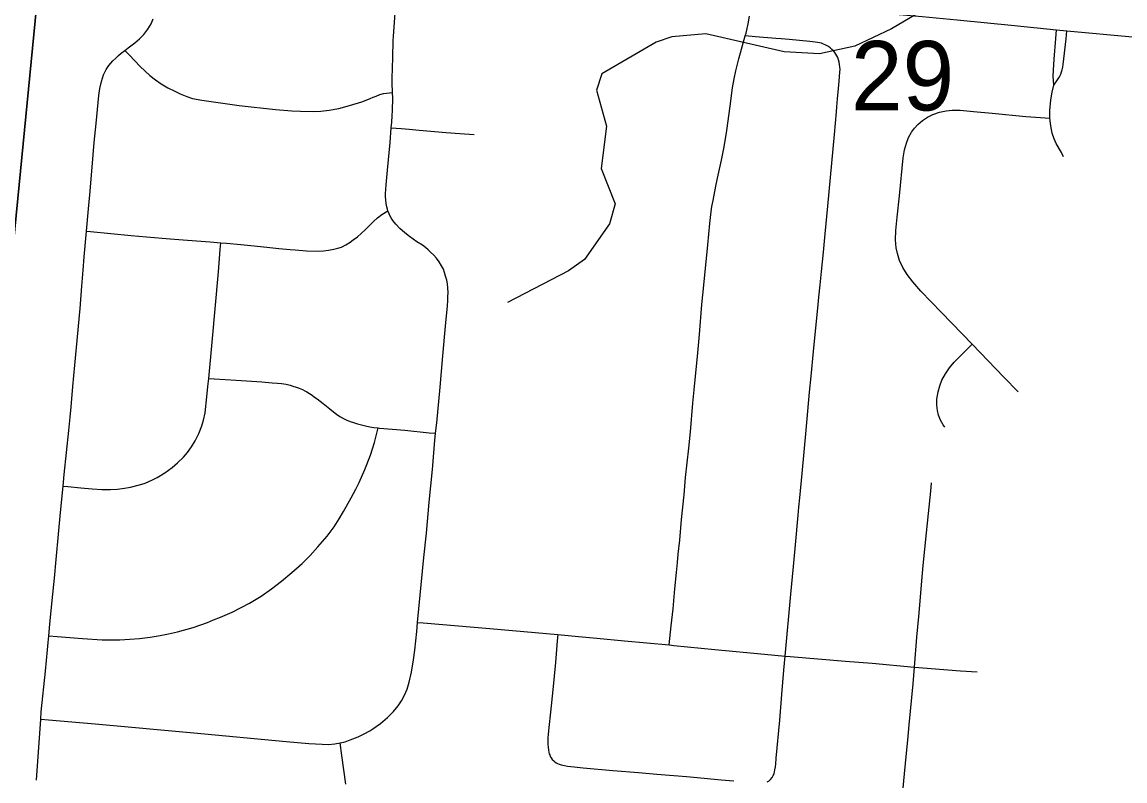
# Model space of a CAD drawing. Extents: x 0 to 34, y 0 to 22.
# Drawn here: x 7.009 to 7.674, y 20.166 to 20.623 of the extents above; entities that cross this region are included whole.
import ezdxf

# ---------------------------------------------------------------- set-up
doc = ezdxf.new("R2010")
doc.units = 0
for name, color, linetype in [('GM_X_City_Street', 7, 'Continuous'), ('GM_X_Corporation', 7, 'Continuous'), ('GM_X_County_Road', 7, 'Continuous'), ('GM_X_Minor_River', 7, 'Continuous'), ('GM_X_Section_Text', 7, 'Continuous')]:
    doc.layers.add(name, color=color, linetype=linetype)

msp = doc.modelspace()

# ---------------------------------------------------------------- linework, layer by layer
at = {"layer": 'GM_X_City_Street'}
for points in [[(7.01765, 20.16616), (7.02028, 20.20299), (7.02059, 20.20733), (7.02311, 20.23181), (7.02439, 20.24474), (7.0248, 20.24906), (7.02517, 20.25317), (7.02578, 20.2602), (7.02715, 20.27441), (7.02852, 20.28798), (7.02955, 20.29912), (7.03104, 20.31451), (7.03224, 20.32749), (7.03378, 20.3434), (7.03445, 20.35036), (7.03714, 20.37693), (7.03794, 20.38497), (7.03856, 20.39114), (7.03966, 20.40351), (7.04072, 20.41641), (7.0418, 20.4269), (7.04391, 20.45041), (7.04501, 20.464), (7.04573, 20.47368), (7.0465, 20.48157), (7.04748, 20.49268), (7.04788, 20.49705), (7.04911, 20.51056), (7.04944, 20.51478), (7.0498, 20.51903), (7.05118, 20.53564), (7.05249, 20.55049), (7.05357, 20.56203), (7.05525, 20.57887), (7.05587, 20.58308), (7.05688, 20.58721), (7.05814, 20.59136), (7.05967, 20.59452), (7.06135, 20.597), (7.06367, 20.59978), (7.06558, 20.60145), (7.06717, 20.60294), (7.06877, 20.60435), (7.07098, 20.60608), (7.07301, 20.60762), (7.07687, 20.61057), (7.07981, 20.61297), (7.08247, 20.61573), (7.08479, 20.61879), (7.08671, 20.62213), (7.08798, 20.62506)], [(7.02028, 20.20299), (7.02498, 20.20258), (7.05303, 20.20009), (7.11249, 20.19461), (7.16815, 20.18948), (7.18179, 20.18821), (7.18987, 20.18778), (7.19371, 20.18768), (7.19751, 20.18804), (7.20083, 20.18865), (7.20367, 20.18938), (7.20682, 20.19045), (7.21162, 20.19236), (7.21606, 20.19457), (7.21788, 20.19558), (7.21853, 20.19588), (7.22038, 20.19703), (7.22496, 20.20024), (7.22927, 20.20392), (7.23283, 20.20751), (7.23565, 20.21093), (7.23779, 20.21409), (7.2396, 20.21745), (7.24105, 20.22096), (7.24234, 20.22519), (7.24373, 20.23132), (7.24494, 20.2387), (7.24568, 20.2446), (7.24693, 20.2557), (7.24745, 20.26125), (7.25116, 20.30033), (7.2528, 20.31513), (7.25448, 20.33368), (7.25634, 20.35336), (7.25652, 20.35582), (7.25759, 20.36865), (7.25828, 20.37526), (7.25892, 20.38148), (7.26093, 20.40296), (7.26261, 20.42201), (7.26432, 20.43983), (7.26536, 20.45208), (7.26559, 20.45529), (7.2657, 20.45766), (7.26585, 20.45985), (7.2657, 20.46285), (7.26541, 20.46533), (7.26496, 20.4676), (7.26431, 20.47001), (7.26365, 20.47227), (7.26299, 20.4741), (7.2619, 20.47622), (7.26051, 20.47863), (7.25891, 20.48075), (7.25715, 20.48264), (7.25525, 20.48447), (7.25379, 20.48586), (7.25226, 20.48724), (7.25029, 20.48863), (7.24699, 20.49059), (7.2425, 20.49383), (7.23964, 20.49616), (7.2367, 20.49872), (7.23436, 20.50127), (7.23256, 20.50354), (7.23152, 20.50514), (7.23071, 20.5066), (7.22983, 20.5085), (7.22957, 20.50935), (7.22925, 20.51035), (7.22888, 20.51171), (7.22845, 20.51376), (7.22823, 20.5158), (7.22808, 20.51792), (7.22815, 20.51982), (7.22823, 20.5223), (7.22837, 20.52494), (7.22919, 20.53381), (7.23084, 20.55047), (7.23158, 20.55941), (7.23186, 20.56288), (7.23218, 20.56661), (7.23231, 20.56973), (7.23239, 20.57723), (7.2323, 20.58074), (7.23217, 20.58652), (7.23237, 20.59824), (7.23241, 20.59887), (7.23247, 20.60197), (7.23272, 20.61188), (7.23288, 20.61466), (7.23386, 20.62847)], [(7.3991, 20.24769), (7.39953, 20.2516), (7.40037, 20.25924), (7.40152, 20.26941), (7.40254, 20.2815), (7.40349, 20.29134), (7.40406, 20.29745), (7.40454, 20.30232), (7.40542, 20.31091), (7.40646, 20.32328), (7.40805, 20.3381), (7.40895, 20.34862), (7.41083, 20.36639), (7.41189, 20.37615), (7.4134, 20.39346), (7.41416, 20.4015), (7.41631, 20.42375), (7.41738, 20.43488), (7.41885, 20.45281), (7.41995, 20.46447), (7.42236, 20.48889), (7.42359, 20.50167), (7.42392, 20.50535), (7.42415, 20.50718), (7.42436, 20.50902), (7.42486, 20.51205), (7.42558, 20.51566), (7.4272, 20.52417), (7.42814, 20.52903), (7.43061, 20.53994), (7.43226, 20.54787), (7.4339, 20.5577), (7.43586, 20.57248), (7.43729, 20.5834), (7.43824, 20.589), (7.43923, 20.59382), (7.44102, 20.60101), (7.44495, 20.61482), (7.44543, 20.61653), (7.44667, 20.62202), (7.44752, 20.6267)], [(7.63088, 20.58506), (7.6307, 20.58817), (7.63061, 20.59039), (7.63079, 20.59404), (7.63122, 20.60069), (7.63212, 20.61315), (7.63251, 20.61852)], [(7.63088, 20.58506), (7.63309, 20.58826), (7.6339, 20.58944), (7.63472, 20.59086), (7.63513, 20.59176), (7.63564, 20.59319), (7.636, 20.59438), (7.63635, 20.59592), (7.63667, 20.59754), (7.63835, 20.61297), (7.63888, 20.61792)], [(7.45927, 20.16574), (7.46021, 20.16657), (7.46114, 20.16774), (7.46183, 20.16896), (7.46229, 20.16997), (7.4626, 20.17115), (7.46285, 20.17243), (7.46309, 20.1742), (7.4633, 20.17585), (7.46358, 20.17951), (7.46585, 20.20233), (7.467, 20.21774), (7.46822, 20.2324), (7.4689, 20.24094), (7.4725, 20.27827), (7.474, 20.29496), (7.4752, 20.30794), (7.47688, 20.32583), (7.47731, 20.33077), (7.47785, 20.3363), (7.47931, 20.35111), (7.48175, 20.37709), (7.4837, 20.39999), (7.48464, 20.40976), (7.48614, 20.42455), (7.48888, 20.45296), (7.48925, 20.45729), (7.49006, 20.4647), (7.49085, 20.47272), (7.49209, 20.48442), (7.49313, 20.49544), (7.49463, 20.5121), (7.49867, 20.55534), (7.49989, 20.56892), (7.50017, 20.57201), (7.50061, 20.57694), (7.50122, 20.58312), (7.50164, 20.58742), (7.50203, 20.59294), (7.50206, 20.59464), (7.50197, 20.59595), (7.50182, 20.59748), (7.50155, 20.59889), (7.50113, 20.60045), (7.50067, 20.6017), (7.50011, 20.60284), (7.49961, 20.60375), (7.49889, 20.6048), (7.49825, 20.60565), (7.49723, 20.60665), (7.4961, 20.60762), (7.49503, 20.60836), (7.49396, 20.609), (7.49313, 20.60944), (7.49207, 20.60987), (7.49083, 20.61032), (7.48966, 20.61062), (7.48844, 20.61085), (7.48718, 20.61106), (7.48382, 20.61151), (7.47146, 20.61266), (7.46653, 20.61308), (7.46344, 20.61331), (7.45107, 20.61432), (7.44495, 20.61482)], [(7.07098, 20.60608), (7.07382, 20.60308), (7.08024, 20.59628), (7.08594, 20.59095), (7.08938, 20.58825), (7.09288, 20.58584), (7.0969, 20.58343), (7.10106, 20.58138), (7.10435, 20.57992), (7.10837, 20.57824), (7.1118, 20.57714), (7.11728, 20.57598), (7.13978, 20.57276), (7.16184, 20.5705), (7.17162, 20.56969), (7.17688, 20.5694), (7.1844, 20.56926), (7.18915, 20.56948), (7.19419, 20.56999), (7.19989, 20.57094), (7.20646, 20.57276), (7.2137, 20.57507), (7.21545, 20.57574), (7.21891, 20.57713), (7.22065, 20.5778), (7.22238, 20.57849), (7.22472, 20.57941), (7.22691, 20.58007), (7.22866, 20.58029), (7.2323, 20.58074)], [(7.63683, 20.54194), (7.63551, 20.54453), (7.63239, 20.54989), (7.63108, 20.5527), (7.62993, 20.55623), (7.62906, 20.56049), (7.62863, 20.5652), (7.62864, 20.56976), (7.6291, 20.57626), (7.62999, 20.58097), (7.63088, 20.58506)], [(7.60944, 20.4002), (7.60074, 20.40906), (7.58178, 20.42896), (7.56327, 20.44803), (7.55079, 20.461), (7.5459, 20.46656), (7.54258, 20.47096), (7.54003, 20.47512), (7.53799, 20.4795), (7.53669, 20.48355), (7.536, 20.48711), (7.53554, 20.49195), (7.53566, 20.49745), (7.53655, 20.50545), (7.53787, 20.51845), (7.54009, 20.54132), (7.54091, 20.54613), (7.54206, 20.55021), (7.54344, 20.55358), (7.54521, 20.55671), (7.54699, 20.55914), (7.549, 20.56136), (7.55173, 20.56373), (7.55475, 20.56572), (7.55798, 20.56736), (7.56194, 20.56882), (7.56607, 20.56971), (7.56968, 20.57004), (7.57457, 20.56999), (7.58257, 20.5692), (7.59372, 20.56818), (7.61415, 20.5662), (7.62287, 20.56559), (7.62863, 20.5652)], [(7.23158, 20.55941), (7.23744, 20.55891), (7.2423, 20.55849), (7.2484, 20.55801), (7.26455, 20.55664), (7.27297, 20.55592), (7.28146, 20.55532)], [(7.04788, 20.49705), (7.05026, 20.49683), (7.07474, 20.49454), (7.08401, 20.49371), (7.09824, 20.4925), (7.10878, 20.49167), (7.12239, 20.49061), (7.12885, 20.49007), (7.13229, 20.48977), (7.14095, 20.48897), (7.14899, 20.48817), (7.15825, 20.48717), (7.16381, 20.48665), (7.1706, 20.48608), (7.17366, 20.4858), (7.18045, 20.48529), (7.18744, 20.48506), (7.19072, 20.48521), (7.19379, 20.48557), (7.19686, 20.48616), (7.19927, 20.48685), (7.20155, 20.48754), (7.20419, 20.48884), (7.20673, 20.49036), (7.20867, 20.49179), (7.2111, 20.49365), (7.21344, 20.49561), (7.2161, 20.49808), (7.21829, 20.50021), (7.22093, 20.50283), (7.22315, 20.50515), (7.22578, 20.50712), (7.22957, 20.50935)], [(7.03378, 20.3434), (7.0366, 20.34313), (7.0444, 20.34239), (7.05121, 20.34174), (7.05699, 20.34138), (7.06224, 20.34135), (7.06651, 20.34162), (7.07076, 20.34218), (7.07438, 20.34283), (7.07975, 20.3441), (7.08321, 20.34524), (7.08767, 20.34722), (7.09036, 20.34863), (7.09506, 20.35151), (7.09952, 20.35473), (7.10276, 20.35752), (7.10624, 20.36095), (7.10862, 20.36373), (7.11119, 20.36714), (7.11342, 20.37077), (7.11557, 20.37515), (7.11738, 20.37969), (7.1184, 20.38319), (7.11929, 20.38761), (7.1204, 20.39721), (7.12106, 20.40342), (7.12153, 20.40829), (7.12367, 20.4302), (7.12732, 20.47256), (7.12849, 20.486), (7.12885, 20.49007)], [(7.56533, 20.37892), (7.56427, 20.38045), (7.56271, 20.38316), (7.56145, 20.38611), (7.56076, 20.38904), (7.56042, 20.39213), (7.5605, 20.39587), (7.56116, 20.40019), (7.56215, 20.40379), (7.56352, 20.40727), (7.56558, 20.41112), (7.56806, 20.41472), (7.57087, 20.41806), (7.57838, 20.42556), (7.58178, 20.42896)], [(7.12153, 20.40829), (7.12485, 20.40808), (7.13814, 20.40723), (7.15359, 20.40622), (7.15974, 20.40566), (7.16292, 20.40542), (7.16528, 20.40517), (7.16809, 20.40477), (7.17063, 20.40417), (7.1723, 20.40371), (7.17412, 20.40314), (7.17602, 20.40247), (7.17805, 20.40158), (7.17936, 20.40089), (7.18073, 20.40017), (7.18222, 20.39923), (7.18382, 20.39821), (7.18535, 20.39713), (7.18682, 20.39608), (7.19051, 20.39317), (7.19458, 20.38994), (7.19869, 20.38666), (7.20089, 20.38521), (7.20265, 20.3842), (7.20441, 20.38335), (7.20671, 20.38245), (7.20877, 20.3818), (7.21116, 20.38104), (7.21359, 20.38034), (7.21609, 20.37969), (7.21865, 20.37924), (7.22106, 20.37883), (7.22372, 20.37851), (7.22446, 20.37841), (7.23966, 20.37706), (7.25446, 20.37563), (7.25828, 20.37526)], [(7.02517, 20.25317), (7.03019, 20.2527), (7.04549, 20.2515), (7.05735, 20.25081), (7.06289, 20.25083), (7.06785, 20.2508), (7.07391, 20.25109), (7.07975, 20.25157), (7.08613, 20.25244), (7.09231, 20.25338), (7.0972, 20.25436), (7.10259, 20.25559), (7.11213, 20.25828), (7.12082, 20.26131), (7.12447, 20.26273), (7.12852, 20.26433), (7.13281, 20.26624), (7.13561, 20.26751), (7.14606, 20.27286), (7.15318, 20.27709), (7.15936, 20.28146), (7.16534, 20.28603), (7.17158, 20.29133), (7.17777, 20.29684), (7.18275, 20.30159), (7.18731, 20.30679), (7.19289, 20.3133), (7.19705, 20.31882), (7.20014, 20.32379), (7.2027, 20.32806), (7.20733, 20.33628), (7.21015, 20.34152), (7.21217, 20.34555), (7.21566, 20.35348), (7.21895, 20.36208), (7.22137, 20.36974), (7.22285, 20.37524), (7.22372, 20.37851)], [(7.53945, 20.15466), (7.54045, 20.16574), (7.54188, 20.1805), (7.54286, 20.19033), (7.54378, 20.19954), (7.54608, 20.22419), (7.54699, 20.23433), (7.54843, 20.25242), (7.54958, 20.26478), (7.55048, 20.27402), (7.55148, 20.28634), (7.55225, 20.29559), (7.55413, 20.31527), (7.55532, 20.32691), (7.55673, 20.34045), (7.5573, 20.34533)], [(7.24745, 20.26125), (7.25087, 20.26097), (7.29096, 20.25756), (7.33191, 20.25388), (7.34448, 20.25275), (7.3554, 20.25184), (7.37224, 20.25024), (7.3991, 20.24769), (7.40181, 20.24743), (7.42667, 20.24493), (7.45663, 20.24212), (7.4689, 20.24094), (7.47207, 20.24062), (7.50535, 20.23781), (7.52138, 20.23671), (7.54699, 20.23433), (7.5747, 20.2321), (7.58473, 20.2315)], [(7.33191, 20.25388), (7.33158, 20.25007), (7.33047, 20.23706), (7.32887, 20.22059), (7.32753, 20.20716), (7.32644, 20.19792), (7.32626, 20.19601), (7.32606, 20.19377), (7.32597, 20.19162), (7.32586, 20.18938), (7.32592, 20.18781), (7.32607, 20.18579), (7.32626, 20.18449), (7.32657, 20.18295), (7.3268, 20.1821), (7.32709, 20.18138), (7.32743, 20.18051), (7.32798, 20.1796), (7.3286, 20.17873)], [(7.20411, 20.16382), (7.20295, 20.17236), (7.20183, 20.18097), (7.20083, 20.18865)], [(7.3286, 20.17873), (7.32953, 20.1778), (7.33017, 20.17722), (7.3309, 20.17672), (7.33169, 20.17624), (7.33281, 20.17575), (7.33393, 20.1754), (7.33588, 20.17496), (7.33774, 20.17467), (7.34184, 20.17414), (7.34721, 20.17358), (7.3651, 20.1721), (7.38058, 20.17086), (7.39168, 20.16972), (7.40952, 20.16833), (7.42012, 20.16739), (7.43047, 20.16632), (7.43814, 20.16569)], [(7.45819, 20.16516), (7.45927, 20.16574)]]:
    msp.add_lwpolyline(points, dxfattribs=at)
at = {"layer": 'GM_X_Corporation'}
for points in [[(7.06384, 21.10587), (6.05195, 21.10587), (5.98271, 20.25288), (6.97134, 20.15852)], [(7.86989, 21.10587), (7.06384, 21.10587), (6.97134, 20.15852), (8.01264, 20.06664), (8.11355, 21.08279)]]:
    msp.add_lwpolyline(points, close=True, dxfattribs=at)
at = {"layer": 'GM_X_County_Road'}
for points in [[(7.5327, 20.62821), (7.53766, 20.62774), (7.55167, 20.62639), (7.5727, 20.62446), (7.60731, 20.6211), (7.63251, 20.61852)], [(7.63251, 20.61852), (7.63888, 20.61792), (7.67845, 20.61415), (7.69697, 20.61236), (7.72693, 20.60947), (7.75065, 20.60764), (7.77354, 20.60552), (7.79397, 20.60361), (7.82122, 20.60123), (7.83791, 20.59959), (7.86201, 20.59712), (7.87251, 20.59615), (7.89043, 20.59443), (7.91577, 20.59199), (7.93432, 20.59031), (7.95956, 20.58775)]]:
    msp.add_lwpolyline(points, dxfattribs=at)
at = {"layer": 'GM_X_Minor_River'}
msp.add_lwpolyline([(7.71009, 20.6633), (7.64885, 20.65505), (7.62629, 20.6464), (7.57273, 20.64256), (7.53319, 20.61906), (7.51097, 20.60851), (7.48964, 20.60401), (7.46842, 20.6052), (7.42122, 20.61602), (7.4007, 20.61416), (7.39115, 20.61094), (7.35852, 20.59186), (7.35529, 20.58206), (7.36131, 20.5603), (7.35814, 20.53494), (7.36644, 20.51351), (7.36316, 20.50143), (7.34794, 20.4801), (7.33832, 20.47309), (7.30152, 20.4541)], dxfattribs=at)

# ---------------------------------------------------------------- texts
at = {"layer": 'GM_X_Section_Text'}
msp.add_text('29', height=0.041856, rotation=0.00001, dxfattribs=at).set_placement((7.50864, 20.56988))

doc.saveas('drawing.dxf')
